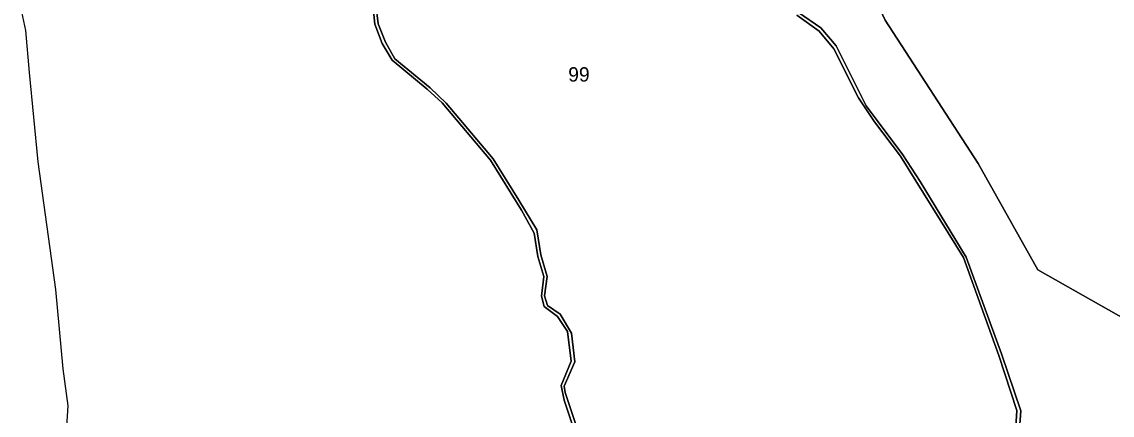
# Model space of a CAD drawing. Extents: x -521939 to -516426, y -1197857 to -1189551.
# Drawn here: x -518731 to -517594, y -1196196 to -1195785 of the extents above; entities that cross this region are included whole.
import ezdxf

# ---------------------------------------------------------------- set-up
doc = ezdxf.new("R2010")
doc.units = 0
for name, color, linetype in [('95620013', 7, 'Continuous'), ('95640013', 7, 'Continuous'), ('95660013', 7, 'Continuous')]:
    doc.layers.add(name, color=color, linetype=linetype)

msp = doc.modelspace()

# ---------------------------------------------------------------- linework, layer by layer
at = {"layer": '95620013'}
for points in [[(-518200.55, -1194967.23), (-518179.17, -1194990.94), (-518161.76, -1195013.8), (-518145.64, -1195041.48), (-518139.37, -1195055.41), (-518125.34, -1195095.33), (-518098.11, -1195230.42), (-518008.6, -1195372.71), (-517919.1, -1195515.01), (-517906.62, -1195540.42), (-517874.16, -1195650.02), (-517841.71, -1195759.62), (-517830.56, -1195783.46), (-517733.42, -1195933.26), (-517671.34, -1196044.27), (-517550.36, -1196112.6)], [(-517550.36, -1196112.6), (-517671.34, -1196044.27), (-517733.42, -1195933.26), (-517830.56, -1195783.46), (-517841.71, -1195759.62), (-517874.16, -1195650.02), (-517906.62, -1195540.42), (-517919.1, -1195515.01), (-518008.6, -1195372.71), (-518098.11, -1195230.42), (-518125.34, -1195095.33), (-518139.37, -1195055.41), (-518145.64, -1195041.48), (-518161.76, -1195013.8), (-518179.17, -1194990.94), (-518200.55, -1194967.23)], [(-518364.73, -1195767.11), (-518362.66, -1195787.64), (-518355.05, -1195808.03), (-518344.62, -1195825.45), (-518307.93, -1195855.73), (-518292.31, -1195870.04), (-518241.94, -1195929.76), (-518209.76, -1195981.75), (-518196.58, -1196005.82), (-518192.59, -1196030.26), (-518186.54, -1196051.19), (-518188.96, -1196071.51), (-518186.06, -1196082.52), (-518172.03, -1196092.68), (-518161.63, -1196108.41), (-518157.88, -1196139.62), (-518168.16, -1196164.78), (-518165.26, -1196180.27), (-518146.88, -1196235.67)], [(-518146.88, -1196235.67), (-518165.26, -1196180.27), (-518168.16, -1196164.78), (-518157.88, -1196139.62), (-518161.63, -1196108.41), (-518172.03, -1196092.68), (-518186.06, -1196082.52), (-518188.96, -1196071.51), (-518186.54, -1196051.19), (-518192.59, -1196030.26), (-518196.58, -1196005.82), (-518209.76, -1195981.75), (-518241.94, -1195929.76), (-518292.31, -1195870.04), (-518307.93, -1195855.73), (-518344.62, -1195825.45), (-518355.05, -1195808.03), (-518362.66, -1195787.64), (-518364.73, -1195767.11)], [(-518143.74, -1196234.22), (-518161.63, -1196179.54), (-518164.29, -1196172.04), (-518165.14, -1196165.39), (-518154.13, -1196140.22), (-518157.4, -1196110.1), (-518169.37, -1196090.5), (-518182.55, -1196081.43), (-518185.82, -1196071.39), (-518182.91, -1196051.07), (-518189.44, -1196028.44), (-518193.68, -1196002.43), (-518212.42, -1195971.47), (-518239.38, -1195928.28), (-518288.12, -1195870.09), (-518304.8, -1195854.12), (-518341.93, -1195823.88), (-518351.6, -1195806.7), (-518359.34, -1195787.34), (-518361.52, -1195767.14)], [(-518361.52, -1195767.14), (-518359.34, -1195787.34), (-518351.6, -1195806.7), (-518341.93, -1195823.88), (-518304.8, -1195854.12), (-518288.12, -1195870.09), (-518239.38, -1195928.28), (-518212.42, -1195971.47), (-518193.68, -1196002.43), (-518189.44, -1196028.44), (-518182.91, -1196051.07), (-518185.82, -1196071.39), (-518182.55, -1196081.43), (-518169.37, -1196090.5), (-518157.4, -1196110.1), (-518154.13, -1196140.22), (-518165.14, -1196165.39), (-518164.29, -1196172.04), (-518161.63, -1196179.54), (-518143.74, -1196234.22)], [(-518684.91, -1196223.86), (-518682.4, -1196186.23), (-518687.78, -1196147.53), (-518695.49, -1196064.81), (-518713.59, -1195931.36), (-518722.87, -1195838.39), (-518726.63, -1195794.44), (-518730.8, -1195775.07)], [(-517922.6, -1195778.43), (-517899.26, -1195795.12), (-517883.9, -1195813.39), (-517858.39, -1195864.8), (-517841.46, -1195889.85), (-517814.61, -1195925.65), (-517748.83, -1196031.14), (-517711.83, -1196133.49), (-517692.97, -1196191.07), (-517694.54, -1196213.69)], [(-517691, -1196219.56), (-517688.82, -1196191.26), (-517709.14, -1196131.74), (-517745.9, -1196030.84), (-517793.9, -1195951.85), (-517812.16, -1195924.15), (-517838.76, -1195888.22), (-517850.37, -1195872.97), (-517881.69, -1195810.43), (-517897.53, -1195791.8), (-517920.87, -1195775.71)]]:
    msp.add_lwpolyline(points, dxfattribs=at)
at = {"layer": '95640013'}
for points in [[(-517694.54, -1196213.69), (-517692.97, -1196191.07), (-517711.83, -1196133.49), (-517748.83, -1196031.14), (-517814.61, -1195925.65), (-517841.46, -1195889.85), (-517858.39, -1195864.8), (-517883.9, -1195813.39), (-517899.26, -1195795.12), (-517922.6, -1195778.43)], [(-517920.87, -1195775.71), (-517897.53, -1195791.8), (-517881.69, -1195810.43), (-517850.37, -1195872.97), (-517838.76, -1195888.22), (-517812.16, -1195924.15), (-517793.9, -1195951.85), (-517745.9, -1196030.84), (-517709.14, -1196131.74), (-517688.82, -1196191.26), (-517691, -1196219.56)]]:
    msp.add_lwpolyline(points, dxfattribs=at)
at = {"layer": '95660013'}
msp.add_lwpolyline([(-518684.91, -1196223.86), (-518682.4, -1196186.23), (-518687.78, -1196147.53), (-518695.49, -1196064.81), (-518713.59, -1195931.36), (-518722.87, -1195838.39), (-518726.63, -1195794.44), (-518730.8, -1195775.07)], dxfattribs=at)

# ---------------------------------------------------------------- texts
msp.add_text('99', height=15, dxfattribs=at).set_placement((-518160.96, -1195847.74))

doc.saveas('drawing.dxf')
